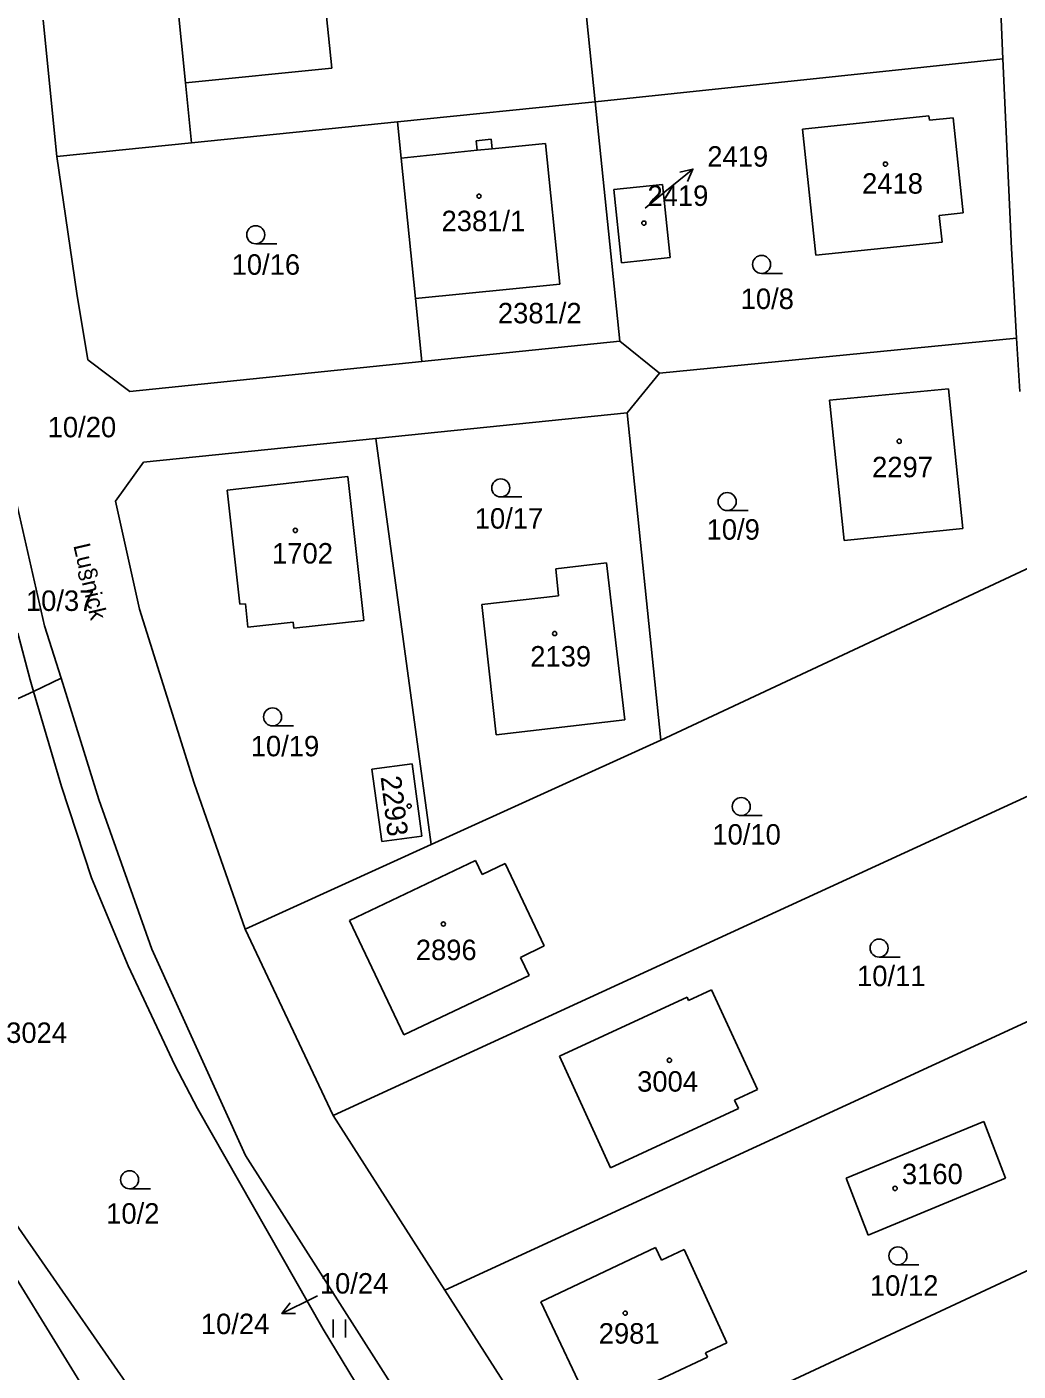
# Model space of a CAD drawing. Extents: x -735249 to -729401, y -1124843 to -1121828.
# Drawn here: x -734910.9 to -734828.6, y -1122687.2 to -1122575.5 of the extents above; entities that cross this region are included whole.
import ezdxf

# ---------------------------------------------------------------- set-up
doc = ezdxf.new("R2010")
doc.units = 0
for name, color, linetype in [('Vrstva 1', 7, 'Continuous'), ('Vrstva 15', 7, 'Continuous'), ('Vrstva 16', 7, 'Continuous'), ('Vrstva 18', 7, 'Continuous'), ('Vrstva 19', 7, 'Continuous'), ('Vrstva 25', 7, 'Continuous'), ('Vrstva 4', 7, 'Continuous')]:
    doc.layers.add(name, color=color, linetype=linetype)

msp = doc.modelspace()

# ---------------------------------------------------------------- linework, layer by layer
at = {"layer": 'Vrstva 1'}
for points in [[(-734863.69, -1122581.74), (-734865.71, -1122561.9)], [(-734886.56, -1122569.25), (-734885.57, -1122578.94)], [(-734898.76, -1122569.99), (-734897.72, -1122580.18)], [(-734829.82, -1122578.19), (-734830.07, -1122572.2)], [(-734908.42, -1122586.3), (-734909.56, -1122574.97)], [(-734863.69, -1122581.74), (-734829.82, -1122578.19)], [(-734829.12, -1122593.93), (-734829.82, -1122578.19)], [(-734885.57, -1122578.94), (-734897.72, -1122580.18)], [(-734897.72, -1122580.18), (-734897.22, -1122585.16)], [(-734863.69, -1122581.74), (-734880.13, -1122583.42)], [(-734861.65, -1122601.63), (-734863.69, -1122581.74)], [(-734835.97, -1122582.91), (-734846.46, -1122584.01)], [(-734835.93, -1122583.28), (-734835.97, -1122582.91)], [(-734833.96, -1122583.07), (-734835.93, -1122583.28)], [(-734833.13, -1122590.98), (-734833.96, -1122583.07)], [(-734880.13, -1122583.42), (-734897.22, -1122585.16)], [(-734880.13, -1122583.42), (-734879.82, -1122586.42)], [(-734846.46, -1122584.01), (-734845.36, -1122594.5)], [(-734908.42, -1122586.3), (-734897.22, -1122585.16)], [(-734873.57, -1122584.98), (-734872.33, -1122584.85)], [(-734873.49, -1122585.78), (-734873.57, -1122584.98)], [(-734872.33, -1122584.85), (-734872.25, -1122585.65)], [(-734872.25, -1122585.65), (-734867.81, -1122585.2)], [(-734867.81, -1122585.2), (-734866.62, -1122596.89)], [(-734908.42, -1122586.3), (-734906.77, -1122597.67)], [(-734879.82, -1122586.42), (-734873.49, -1122585.78)], [(-734879.82, -1122586.42), (-734878.63, -1122598.09)], [(-734862.14, -1122589.04), (-734858.11, -1122588.63)], [(-734858.11, -1122588.63), (-734857.46, -1122594.7)], [(-734861.5, -1122595.12), (-734862.14, -1122589.04)], [(-734835.11, -1122591.19), (-734833.13, -1122590.98)], [(-734834.87, -1122593.4), (-734835.11, -1122591.19)], [(-734845.36, -1122594.5), (-734834.87, -1122593.4)], [(-734828.69, -1122601.4), (-734829.12, -1122593.93)], [(-734857.46, -1122594.7), (-734861.5, -1122595.12)], [(-734906.77, -1122597.67), (-734905.84, -1122603.18)], [(-734866.62, -1122596.89), (-734878.63, -1122598.09)], [(-734878.63, -1122598.09), (-734878.1, -1122603.32)], [(-734878.1, -1122603.32), (-734861.65, -1122601.63)], [(-734858.36, -1122604.31), (-734861.65, -1122601.63)], [(-734858.36, -1122604.31), (-734828.69, -1122601.4)], [(-734828.43, -1122605.81), (-734828.69, -1122601.4)], [(-734905.84, -1122603.18), (-734902.37, -1122605.82)], [(-734902.37, -1122605.82), (-734878.1, -1122603.32)], [(-734861.05, -1122607.6), (-734858.36, -1122604.31)], [(-734844.22, -1122606.55), (-734834.33, -1122605.59)], [(-734843.02, -1122618.22), (-734844.22, -1122606.55)], [(-734834.33, -1122605.59), (-734833.16, -1122617.21)], [(-734861.05, -1122607.6), (-734881.93, -1122609.73)], [(-734858.25, -1122634.81), (-734861.05, -1122607.6)], [(-734881.93, -1122609.73), (-734901.23, -1122611.71)], [(-734881.93, -1122609.73), (-734877.33, -1122643.48)], [(-734909.45, -1122625.29), (-734912.9, -1122610.07)], [(-734901.23, -1122611.71), (-734903.55, -1122614.95)], [(-734884.24, -1122612.9), (-734894.28, -1122614.02)], [(-734882.92, -1122624.85), (-734884.24, -1122612.9)], [(-734894.28, -1122614.02), (-734893.23, -1122623.51)], [(-734903.55, -1122614.95), (-734901.55, -1122623.92)], [(-734833.16, -1122617.21), (-734843.02, -1122618.22)], [(-734825.77, -1122619.59), (-734858.25, -1122634.81)], [(-734866.97, -1122620.57), (-734862.76, -1122620.07)], [(-734866.75, -1122622.8), (-734866.97, -1122620.57)], [(-734862.76, -1122620.07), (-734861.22, -1122633.1)], [(-734873.1, -1122623.53), (-734866.75, -1122622.8)], [(-734901.55, -1122623.92), (-734897.02, -1122638.38)], [(-734893.23, -1122623.51), (-734892.76, -1122623.46)], [(-734892.76, -1122623.46), (-734892.54, -1122625.4)], [(-734871.91, -1122634.36), (-734873.1, -1122623.53)], [(-734909.45, -1122625.29), (-734908.07, -1122629.65)], [(-734892.54, -1122625.4), (-734888.78, -1122624.98)], [(-734888.78, -1122624.98), (-734888.73, -1122625.49)], [(-734888.73, -1122625.49), (-734882.92, -1122624.85)], [(-734911.65, -1122625.92), (-734910.64, -1122629.79)], [(-734910.64, -1122629.79), (-734910.35, -1122630.75)], [(-734910.35, -1122630.75), (-734908.07, -1122629.65)], [(-734908.07, -1122629.65), (-734904.92, -1122639.74)], [(-734929.94, -1122639.69), (-734910.35, -1122630.75)], [(-734910.35, -1122630.75), (-734908.02, -1122638.64)], [(-734861.22, -1122633.1), (-734871.91, -1122634.36)], [(-734877.33, -1122643.48), (-734858.25, -1122634.81)], [(-734878.91, -1122636.77), (-734882.24, -1122637.22)], [(-734878.1, -1122642.78), (-734878.91, -1122636.77)], [(-734885.47, -1122665.98), (-734823.89, -1122637.68)], [(-734882.24, -1122637.22), (-734881.43, -1122643.23)], [(-734908.02, -1122638.64), (-734905.53, -1122646.24)], [(-734897.02, -1122638.38), (-734892.78, -1122650.51)], [(-734904.92, -1122639.74), (-734900.54, -1122652.18)], [(-734892.78, -1122650.51), (-734877.33, -1122643.48)], [(-734881.43, -1122643.23), (-734878.1, -1122642.78)], [(-734873.65, -1122644.8), (-734884.11, -1122649.78)], [(-734873.09, -1122645.97), (-734873.65, -1122644.8)], [(-734871.18, -1122645.06), (-734873.09, -1122645.97)], [(-734867.94, -1122651.88), (-734871.18, -1122645.06)], [(-734905.53, -1122646.24), (-734902.5, -1122653.55)], [(-734884.11, -1122649.78), (-734879.59, -1122659.29)], [(-734892.78, -1122650.51), (-734885.47, -1122665.98)], [(-734900.54, -1122652.18), (-734892.74, -1122669.32)], [(-734869.9, -1122652.85), (-734867.94, -1122651.88)], [(-734902.5, -1122653.55), (-734898.62, -1122661.82)], [(-734869.18, -1122654.35), (-734869.9, -1122652.85)], [(-734879.59, -1122659.29), (-734869.18, -1122654.35)], [(-734854.02, -1122655.55), (-734855.94, -1122656.43)], [(-734850.21, -1122663.82), (-734854.02, -1122655.55)], [(-734876.19, -1122680.5), (-734824.41, -1122656.62)], [(-734856.06, -1122656.16), (-734866.66, -1122661.06)], [(-734855.94, -1122656.43), (-734856.06, -1122656.16)], [(-734922.89, -1122659.09), (-734889.48, -1122707.24)], [(-734866.66, -1122661.06), (-734862.42, -1122670.33)], [(-734898.62, -1122661.82), (-734896.74, -1122665.41)], [(-734852.12, -1122664.71), (-734850.21, -1122663.82)], [(-734851.78, -1122665.42), (-734852.12, -1122664.71)], [(-734896.74, -1122665.41), (-734886.3, -1122683.75)], [(-734862.42, -1122670.33), (-734851.78, -1122665.42)], [(-734885.47, -1122665.98), (-734876.19, -1122680.5)], [(-734842.85, -1122671.19), (-734831.4, -1122666.48)], [(-734831.4, -1122666.48), (-734829.6, -1122671.2)], [(-734917.59, -1122670.16), (-734882.26, -1122727.61)], [(-734892.74, -1122669.32), (-734862.81, -1122716.3)], [(-734842.85, -1122671.19), (-734841.03, -1122675.93)], [(-734829.6, -1122671.2), (-734841.03, -1122675.93)], [(-734818.35, -1122674.46), (-734865.87, -1122696.65)], [(-734868.22, -1122681.48), (-734858.69, -1122676.95)], [(-734858.69, -1122676.95), (-734858.18, -1122678.02)], [(-734858.18, -1122678.02), (-734856.31, -1122677.14)], [(-734856.31, -1122677.14), (-734852.77, -1122684.88)], [(-734865.87, -1122696.65), (-734876.19, -1122680.5)], [(-734863.91, -1122690.57), (-734868.22, -1122681.48)], [(-734868.69, -1122712.81), (-734886.3, -1122683.75)], [(-734852.77, -1122684.88), (-734854.54, -1122685.72)], [(-734854.54, -1122685.72), (-734854.37, -1122686.08)], [(-734854.37, -1122686.08), (-734863.91, -1122690.57)]]:
    msp.add_lwpolyline(points, dxfattribs=at)
at = {"layer": 'Vrstva 16'}
for points in [[(-734859.55, -1122590.6), (-734857.9, -1122589.24)], [(-734886.77, -1122680.99), (-734887.03, -1122681.12)]]:
    msp.add_lwpolyline(points, dxfattribs=at)
at = {"layer": 'Vrstva 25'}
for points in [[(-734857.9, -1122589.24), (-734855.579, -1122587.34)], [(-734856.67, -1122587.587), (-734855.579, -1122587.34), (-734856.036, -1122588.361)], [(-734891.9, -1122593.55), (-734890.15, -1122593.55)], [(-734849.87, -1122596.01), (-734848.12, -1122596.01)], [(-734871.54, -1122614.59), (-734869.79, -1122614.59)], [(-734852.73, -1122615.72), (-734850.98, -1122615.72)], [(-734890.5, -1122633.62), (-734888.75, -1122633.62)], [(-734851.56, -1122641.07), (-734849.81, -1122641.07)], [(-734840.11, -1122652.83), (-734838.36, -1122652.83)], [(-734902.38, -1122672.08), (-734900.63, -1122672.08)], [(-734838.55, -1122678.41), (-734836.8, -1122678.41)], [(-734887.03, -1122681.12), (-734889.717, -1122682.453)], [(-734888.599, -1122682.457), (-734889.717, -1122682.453), (-734889.043, -1122681.561)], [(-734885.467, -1122684.435), (-734885.467, -1122682.935)], [(-734884.433, -1122684.435), (-734884.433, -1122682.935)]]:
    msp.add_lwpolyline(points, dxfattribs=at)
for centre, radius in [((-734839.58, -1122586.93), 0.175), ((-734873.35, -1122589.59), 0.175), ((-734891.9, -1122592.8), 0.75), ((-734859.65, -1122591.83), 0.175), ((-734849.87, -1122595.26), 0.75), ((-734838.44, -1122609.96), 0.175), ((-734871.54, -1122613.84), 0.75), ((-734852.73, -1122614.97), 0.75), ((-734888.61, -1122617.37), 0.175), ((-734867.06, -1122625.94), 0.175), ((-734890.5, -1122632.87), 0.75), ((-734879.15, -1122640.28), 0.175), ((-734851.56, -1122640.32), 0.75), ((-734876.31, -1122650.08), 0.175), ((-734840.11, -1122652.08), 0.75), ((-734857.53, -1122661.4), 0.175), ((-734902.38, -1122671.33), 0.75), ((-734838.78, -1122672.05), 0.175), ((-734838.55, -1122677.66), 0.75), ((-734861.2, -1122682.42), 0.175)]:
    msp.add_circle(centre, radius, dxfattribs=at)
at = {"layer": 'Vrstva 4'}
msp.add_lwpolyline([(-734873.49, -1122585.78), (-734872.25, -1122585.65)], dxfattribs=at)

# ---------------------------------------------------------------- texts
at = {"layer": 'Vrstva 15'}
msp.add_text('Lu§nick\xa0', height=1.4, rotation=283.10225, dxfattribs=at).set_placement((-734907.06, -1122618.619))
at = {"layer": 'Vrstva 16'}
for s, p in [('2419', (-734854.38, -1122587.14)), ('3024', (-734912.63, -1122659.96)), ('10/24', (-734896.456, -1122684.16))]:
    msp.add_text(s, height=1.7, dxfattribs=at).set_placement(p)
at = {"layer": 'Vrstva 18'}
for s, p in [('10/16', (-734893.9, -1122596.12)), ('10/8', (-734851.61, -1122598.97)), ('10/20', (-734909.18, -1122609.63)), ('10/17', (-734873.7, -1122617.22)), ('10/9', (-734854.44, -1122618.14)), ('10/37', (-734910.99, -1122624.06)), ('10/19', (-734892.31, -1122636.14)), ('10/10', (-734853.96, -1122643.48)), ('10/11', (-734841.94, -1122655.24)), ('10/2', (-734904.32, -1122674.98)), ('10/24', (-734886.57, -1122680.79)), ('10/12', (-734840.87, -1122680.97))]:
    msp.add_text(s, height=1.7, dxfattribs=at).set_placement(p)
at = {"layer": 'Vrstva 19'}
for s, p in [('2419', (-734859.35, -1122590.4)), ('2418', (-734841.52, -1122589.38)), ('2381/1', (-734876.46, -1122592.5)), ('2381/2', (-734871.78, -1122600.16)), ('2297', (-734840.69, -1122612.95)), ('1702', (-734890.54, -1122620.12)), ('2139', (-734869.09, -1122628.68)), ('2896', (-734878.6, -1122653.08)), ('3004', (-734860.21, -1122664.01)), ('3160', (-734838.213, -1122671.7)), ('2981', (-734863.4, -1122684.95))]:
    msp.add_text(s, height=1.7, dxfattribs=at).set_placement(p)
msp.add_text('2293', height=1.7, rotation=277.0022, dxfattribs=at).set_placement((-734881.528, -1122637.854))

doc.saveas('drawing.dxf')
